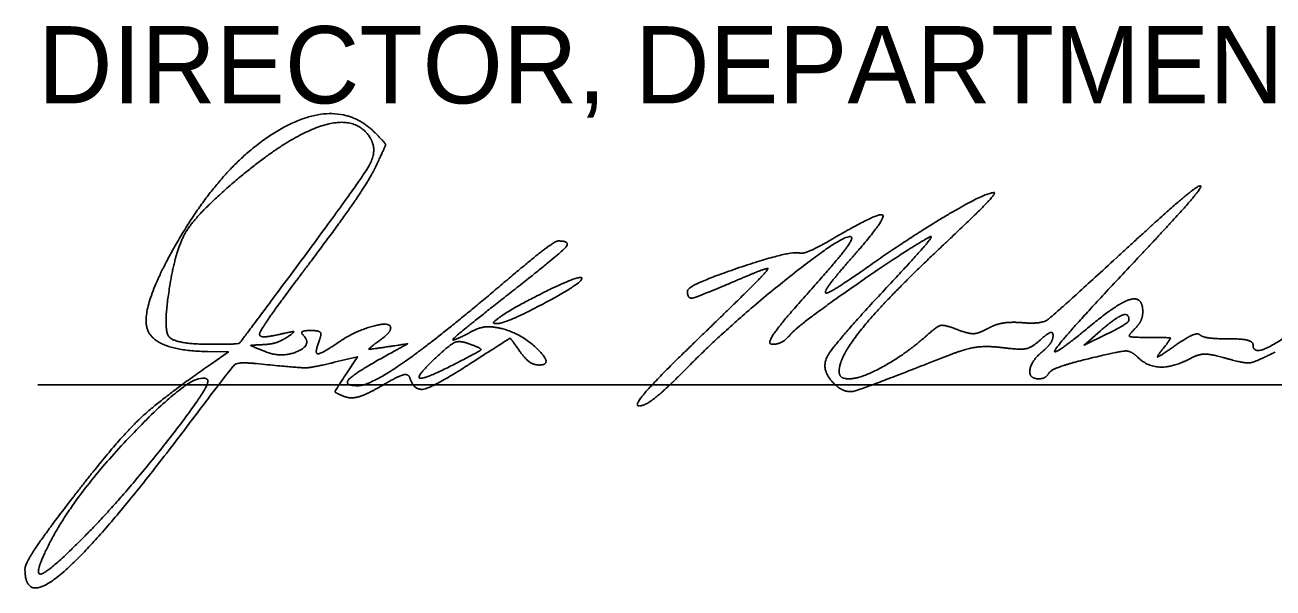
# Model space of a CAD drawing. Extents: x -4 to 116, y -17 to 29.
# Drawn here: x 72.988 to 75.249, y -6.369 to -5.348 of the extents above; entities that cross this region are included whole.
import ezdxf

# ---------------------------------------------------------------- set-up
doc = ezdxf.new("R2010")
doc.units = 0
doc.layers.add('SH_Data', color=7, linetype='Continuous')
doc.layers.add('SH_Text', color=7, linetype='Continuous')

msp = doc.modelspace()

# ---------------------------------------------------------------- linework, layer by layer
at = {"layer": 'SH_Data'}
msp.add_line((73.0112, -6.0003), (76.5112, -6.0003), dxfattribs=at)
at = {"layer": 'SH_Text'}
for p, q in [((73.4735, -5.7952), (73.4735, -5.7952)), ((73.8388, -5.8851), (73.8388, -5.8851)), ((74.9878, -5.8831), (74.9878, -5.8831)), ((74.2106, -5.9141), (74.2106, -5.9141)), ((73.794, -5.9267), (73.794, -5.9267))]:
    msp.add_line(p, q, dxfattribs=at)
for points in [[(74.936, -5.9027), (74.9065, -5.9284), (74.9471, -5.9087)], [(73.3258, -5.9622), (73.3565, -5.9409), (73.3187, -5.9403)], [(73.5688, -5.982), (73.59, -5.9497), (73.5482, -5.9597)]]:
    msp.add_lwpolyline(points, dxfattribs=at)
for points in [[(73.2622, -5.7444), (73.3484, -5.5941), (73.5565, -5.478), (73.6222, -5.5437)], [(73.6132, -5.5529), (73.5873, -5.5109), (73.4612, -5.552), (73.3658, -5.6337)], [(73.4735, -5.7952), (73.5948, -5.6318), (73.6272, -5.5756), (73.6132, -5.5529)], [(73.6222, -5.5437), (73.641, -5.5625), (73.641, -5.5675), (73.6227, -5.6059)], [(73.6227, -5.6059), (73.6117, -5.6289), (73.56, -5.7045), (73.5078, -5.7739)], [(73.3658, -5.6337), (73.2992, -5.6907), (73.2603, -5.7548), (73.2493, -5.8261)], [(74.5159, -5.786), (74.5964, -5.7294), (74.7277, -5.6521), (74.7434, -5.6521)], [(74.7434, -5.6521), (74.7483, -5.6521), (74.707, -5.6947), (74.6517, -5.7468)], [(74.9702, -5.7656), (75.0452, -5.6965), (75.1112, -5.6399), (75.1169, -5.6398)], [(75.1169, -5.6398), (75.1227, -5.6397), (75.0706, -5.6999), (75.0013, -5.7735)], [(74.4569, -5.7325), (74.5357, -5.6863), (74.5479, -5.6996), (74.4887, -5.7669)], [(73.8523, -5.8179), (73.9027, -5.7751), (73.9482, -5.7399), (73.9534, -5.7398)], [(73.9534, -5.7398), (73.9782, -5.7393), (73.9549, -5.7649), (73.869, -5.8321)], [(74.485, -5.7327), (74.4754, -5.7231), (74.2657, -5.89), (74.1878, -5.9693)], [(74.6253, -5.7332), (74.5762, -5.7609), (74.3879, -5.8932), (74.3747, -5.9091)], [(74.3913, -5.7617), (74.3969, -5.7635), (74.4264, -5.7504), (74.4569, -5.7325)], [(74.4072, -5.8331), (74.4535, -5.7814), (74.4885, -5.7362), (74.485, -5.7327)], [(74.5601, -5.8121), (74.6062, -5.7628), (74.6356, -5.7273), (74.6253, -5.7332)], [(73.3187, -5.9403), (73.2207, -5.9386), (73.1973, -5.8575), (73.2622, -5.7444)], [(74.188, -5.8303), (74.1882, -5.8197), (74.3756, -5.7565), (74.3913, -5.7617)], [(74.6517, -5.7468), (74.552, -5.8406), (74.4628, -5.9487), (74.4628, -5.9757)], [(74.7952, -5.8879), (74.8286, -5.8908), (74.8521, -5.8743), (74.9702, -5.7656)], [(73.5078, -5.7739), (73.4555, -5.8432), (73.4128, -5.9039), (73.4128, -5.9087)], [(74.4887, -5.7669), (74.4607, -5.7987), (74.4378, -5.8284), (74.4378, -5.8328)], [(74.4378, -5.8328), (74.4378, -5.8373), (74.4729, -5.8162), (74.5159, -5.786)], [(75.0013, -5.7735), (74.8718, -5.911), (74.8397, -5.9583), (74.9219, -5.8905)], [(73.3273, -5.9271), (73.374, -5.9271), (73.3786, -5.923), (73.4735, -5.7952)], [(73.8388, -5.8851), (73.8592, -5.8672), (73.9912, -5.8014), (73.9964, -5.8066)], [(73.9964, -5.8066), (74.0026, -5.8128), (73.86, -5.8896), (73.8423, -5.8896)], [(74.2106, -5.9141), (74.2816, -5.8456), (74.3369, -5.7896), (74.3335, -5.7896)], [(74.3335, -5.7896), (74.3301, -5.7896), (74.3011, -5.8009), (74.269, -5.8146)], [(73.2493, -5.8261), (73.2378, -5.8994), (73.2592, -5.9271), (73.3273, -5.9271)], [(73.5909, -6.0021), (73.614, -6.0021), (73.74, -5.9133), (73.8523, -5.8179)], [(73.869, -5.8321), (73.7758, -5.9052), (73.7543, -5.9267), (73.7982, -5.9032)], [(74.269, -5.8146), (74.2064, -5.8415), (74.1876, -5.8451), (74.188, -5.8303)], [(74.3414, -5.9271), (74.3311, -5.9271), (74.36, -5.8858), (74.4072, -5.8331)], [(74.453, -5.9977), (74.4278, -5.9725), (74.4567, -5.9224), (74.5601, -5.8121)], [(75.2128, -5.9286), (75.2128, -5.9515), (75.308, -5.89), (75.3784, -5.8218)], [(74.9219, -5.8905), (74.9703, -5.8506), (75.0128, -5.8403), (75.0128, -5.8684)], [(74.9878, -5.8831), (74.9878, -5.8696), (74.9637, -5.8787), (74.936, -5.9027)], [(75.0128, -5.8684), (75.0128, -5.8773), (75.006, -5.8914), (74.9978, -5.8996)], [(73.5569, -5.9227), (73.5857, -5.903), (73.6503, -5.8854), (73.6503, -5.8974)], [(73.6503, -5.8974), (73.6503, -5.9019), (73.6405, -5.9127), (73.6286, -5.9214)], [(73.7982, -5.9032), (73.8109, -5.8964), (73.8348, -5.8944), (73.8514, -5.8986)], [(73.8423, -5.8896), (73.8375, -5.8896), (73.8359, -5.8876), (73.8388, -5.8851)], [(73.8514, -5.8986), (73.8875, -5.9077), (73.9458, -5.9646), (73.9191, -5.9646)], [(74.6203, -5.9121), (74.6405, -5.8941), (74.6534, -5.8915), (74.6772, -5.9005)], [(74.6772, -5.9005), (74.6973, -5.9082), (74.7161, -5.9074), (74.7322, -5.8984)], [(74.7322, -5.8984), (74.7456, -5.8909), (74.7739, -5.8862), (74.7952, -5.8879)], [(74.9471, -5.9087), (74.9695, -5.8978), (74.9878, -5.8863), (74.9878, -5.8831)], [(74.9978, -5.8996), (74.9861, -5.9113), (74.992, -5.9146), (75.0243, -5.9146)], [(73.4128, -5.9087), (73.4128, -5.9134), (73.4282, -5.9137), (73.4471, -5.9094)], [(73.4628, -5.9141), (73.4524, -5.921), (73.4328, -5.9272), (73.419, -5.9277)], [(73.4232, -5.9404), (73.4531, -5.9524), (73.5093, -5.9278), (73.4918, -5.9104)], [(73.4471, -5.9094), (73.4726, -5.9034), (73.4767, -5.9046), (73.4628, -5.9141)], [(73.4918, -5.9104), (73.4873, -5.9058), (73.4936, -5.9021), (73.5058, -5.9021)], [(73.5058, -5.9021), (73.5203, -5.9021), (73.5255, -5.9086), (73.5207, -5.9209)], [(73.5207, -5.9209), (73.5118, -5.9441), (73.5246, -5.9448), (73.5569, -5.9227)], [(73.6286, -5.9214), (73.6097, -5.9353), (73.6117, -5.9366), (73.6442, -5.9316)], [(73.794, -5.9267), (73.7768, -5.9204), (73.7603, -5.9255), (73.7409, -5.9433)], [(73.8844, -5.94), (73.8675, -5.9159), (73.8655, -5.9163), (73.7997, -5.9587)], [(74.1003, -6.0389), (74.0899, -6.0387), (74.1396, -5.9826), (74.2106, -5.9141)], [(74.3747, -5.9091), (74.3664, -5.919), (74.3514, -5.9271), (74.3414, -5.9271)], [(74.4808, -5.9896), (74.5025, -5.9896), (74.5839, -5.9444), (74.6203, -5.9121)], [(74.8277, -5.9187), (74.812, -5.9329), (74.7908, -5.9373), (74.7582, -5.9331)], [(74.8503, -5.9112), (74.8503, -5.9041), (74.8401, -5.9074), (74.8277, -5.9187)], [(74.8315, -5.9396), (74.8418, -5.9311), (74.8503, -5.9183), (74.8503, -5.9112)], [(75.0243, -5.9146), (75.0618, -5.9146), (75.0642, -5.9167), (75.0487, -5.936)], [(75.0704, -5.9301), (75.0918, -5.9151), (75.1125, -5.9061), (75.1165, -5.91)], [(75.1165, -5.91), (75.1204, -5.9139), (75.1437, -5.9171), (75.1682, -5.9171)], [(75.1682, -5.9171), (75.1927, -5.9171), (75.2128, -5.9223), (75.2128, -5.9286)], [(73.419, -5.9277), (73.3966, -5.9286), (73.397, -5.9299), (73.4232, -5.9404)], [(73.6442, -5.9316), (73.681, -5.9261), (73.6809, -5.9263), (73.6354, -5.9514)], [(73.7409, -5.9433), (73.6966, -5.9837), (73.7079, -5.9926), (73.7659, -5.963)], [(73.7659, -5.963), (73.8123, -5.9394), (73.8158, -5.9347), (73.794, -5.9267)], [(73.9191, -5.9646), (73.9095, -5.9646), (73.8939, -5.9535), (73.8844, -5.94)], [(74.7582, -5.9331), (74.729, -5.9294), (74.6891, -5.9358), (74.6526, -5.9502)], [(74.8245, -5.9896), (74.8061, -5.9896), (74.8107, -5.9569), (74.8315, -5.9396)], [(75.0032, -5.95), (74.992, -5.9389), (74.972, -5.9394), (74.9188, -5.9522)], [(75.0487, -5.936), (75.0366, -5.951), (75.0431, -5.9493), (75.0704, -5.9301)], [(75.164, -5.9525), (75.1371, -5.9448), (75.114, -5.9448), (75.0995, -5.9525)], [(75.253, -5.9411), (75.2157, -5.9596), (75.1971, -5.962), (75.164, -5.9525)], [(73.0749, -6.2043), (73.1525, -6.1039), (73.2326, -6.0266), (73.3258, -5.9622)], [(73.407, -5.9621), (73.3736, -5.9587), (73.3619, -5.9692), (73.2852, -6.0709)], [(73.5482, -5.9597), (73.5079, -5.9695), (73.4855, -5.9699), (73.407, -5.9621)], [(73.6354, -5.9514), (73.5844, -5.9797), (73.5646, -6.0021), (73.5909, -6.0021)], [(73.7997, -5.9587), (73.7309, -6.0031), (73.6934, -6.0128), (73.6853, -5.9884)], [(74.6526, -5.9502), (74.5066, -6.0079), (74.4715, -6.0163), (74.453, -5.9977)], [(74.9188, -5.9522), (74.8805, -5.9614), (74.8462, -5.9736), (74.8427, -5.9793)], [(75.0995, -5.9525), (75.0687, -5.969), (75.0209, -5.9678), (75.0032, -5.95)], [(73.3187, -5.9914), (73.2978, -5.9705), (73.0793, -6.1962), (73.0329, -6.2865)], [(73.1031, -6.2678), (73.1706, -6.1987), (73.3264, -5.9991), (73.3187, -5.9914)], [(73.5676, -6.022), (73.5494, -6.0151), (73.5495, -6.0114), (73.5688, -5.982)], [(73.6853, -5.9884), (73.6824, -5.9799), (73.6632, -5.9851), (73.6341, -6.0022)], [(74.1878, -5.9693), (74.1499, -6.0078), (74.1106, -6.0391), (74.1003, -6.0389)], [(74.4628, -5.9757), (74.4628, -5.9834), (74.4709, -5.9896), (74.4808, -5.9896)], [(74.8427, -5.9793), (74.8392, -5.985), (74.831, -5.9896), (74.8245, -5.9896)], [(73.6341, -6.0022), (73.6085, -6.0174), (73.5786, -6.0263), (73.5676, -6.022)], [(73.2852, -6.0709), (73.1329, -6.273), (72.9878, -6.4016), (72.9878, -6.3346)], [(72.9878, -6.3346), (72.9878, -6.325), (73.027, -6.2664), (73.0749, -6.2043)], [(73.0329, -6.2865), (73.0017, -6.3475), (73.0333, -6.339), (73.1031, -6.2678)]]:
    msp.add_open_spline(points, degree=2, dxfattribs=at)

# ---------------------------------------------------------------- texts
msp.add_text('DIRECTOR, DEPARTMENT OF TRANSPORTATION', height=0.14, dxfattribs=at).set_placement((73.0112, -5.4903))

doc.saveas('drawing.dxf')
